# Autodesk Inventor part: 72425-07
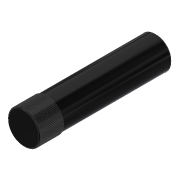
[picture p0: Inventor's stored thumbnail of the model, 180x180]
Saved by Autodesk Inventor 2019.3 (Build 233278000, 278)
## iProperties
Created: 2013-06
Part Number: 72425-07
Material: Ogólny
Document SubType Name: Modeling
Designer: CADENGINEERING4
Density: 1 g/cm^3
Appearance: Gładki — czarny
Author: CADENGINEERING4
Revision Number: ÈÎºÎ
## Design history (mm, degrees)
feature "ÊäÈë1"
node "Bryła1"
